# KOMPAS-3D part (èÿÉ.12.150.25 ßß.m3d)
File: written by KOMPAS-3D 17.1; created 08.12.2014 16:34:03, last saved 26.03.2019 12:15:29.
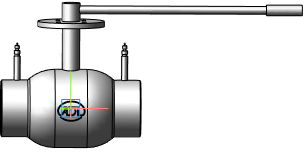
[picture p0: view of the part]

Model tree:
1. Операция без истории:6  (labels: Сталь 20  ГОСТ 1050-88)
